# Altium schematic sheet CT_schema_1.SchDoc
size 886 x 812 mm
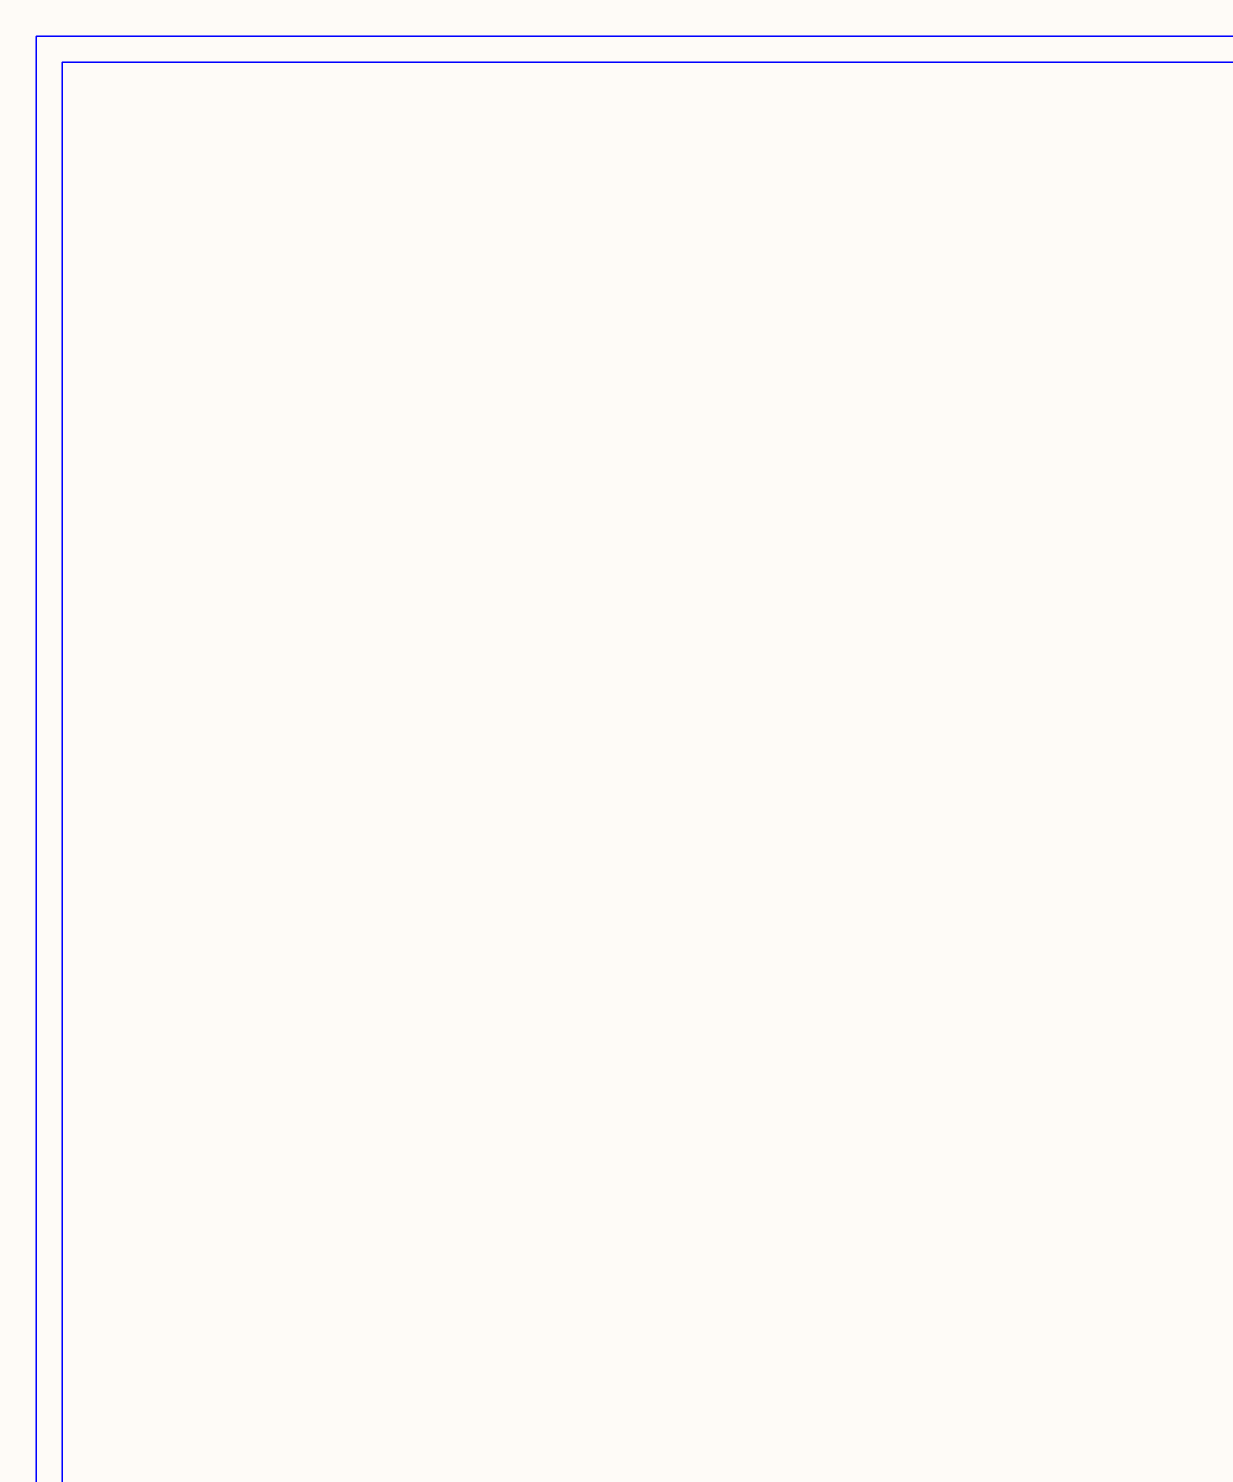
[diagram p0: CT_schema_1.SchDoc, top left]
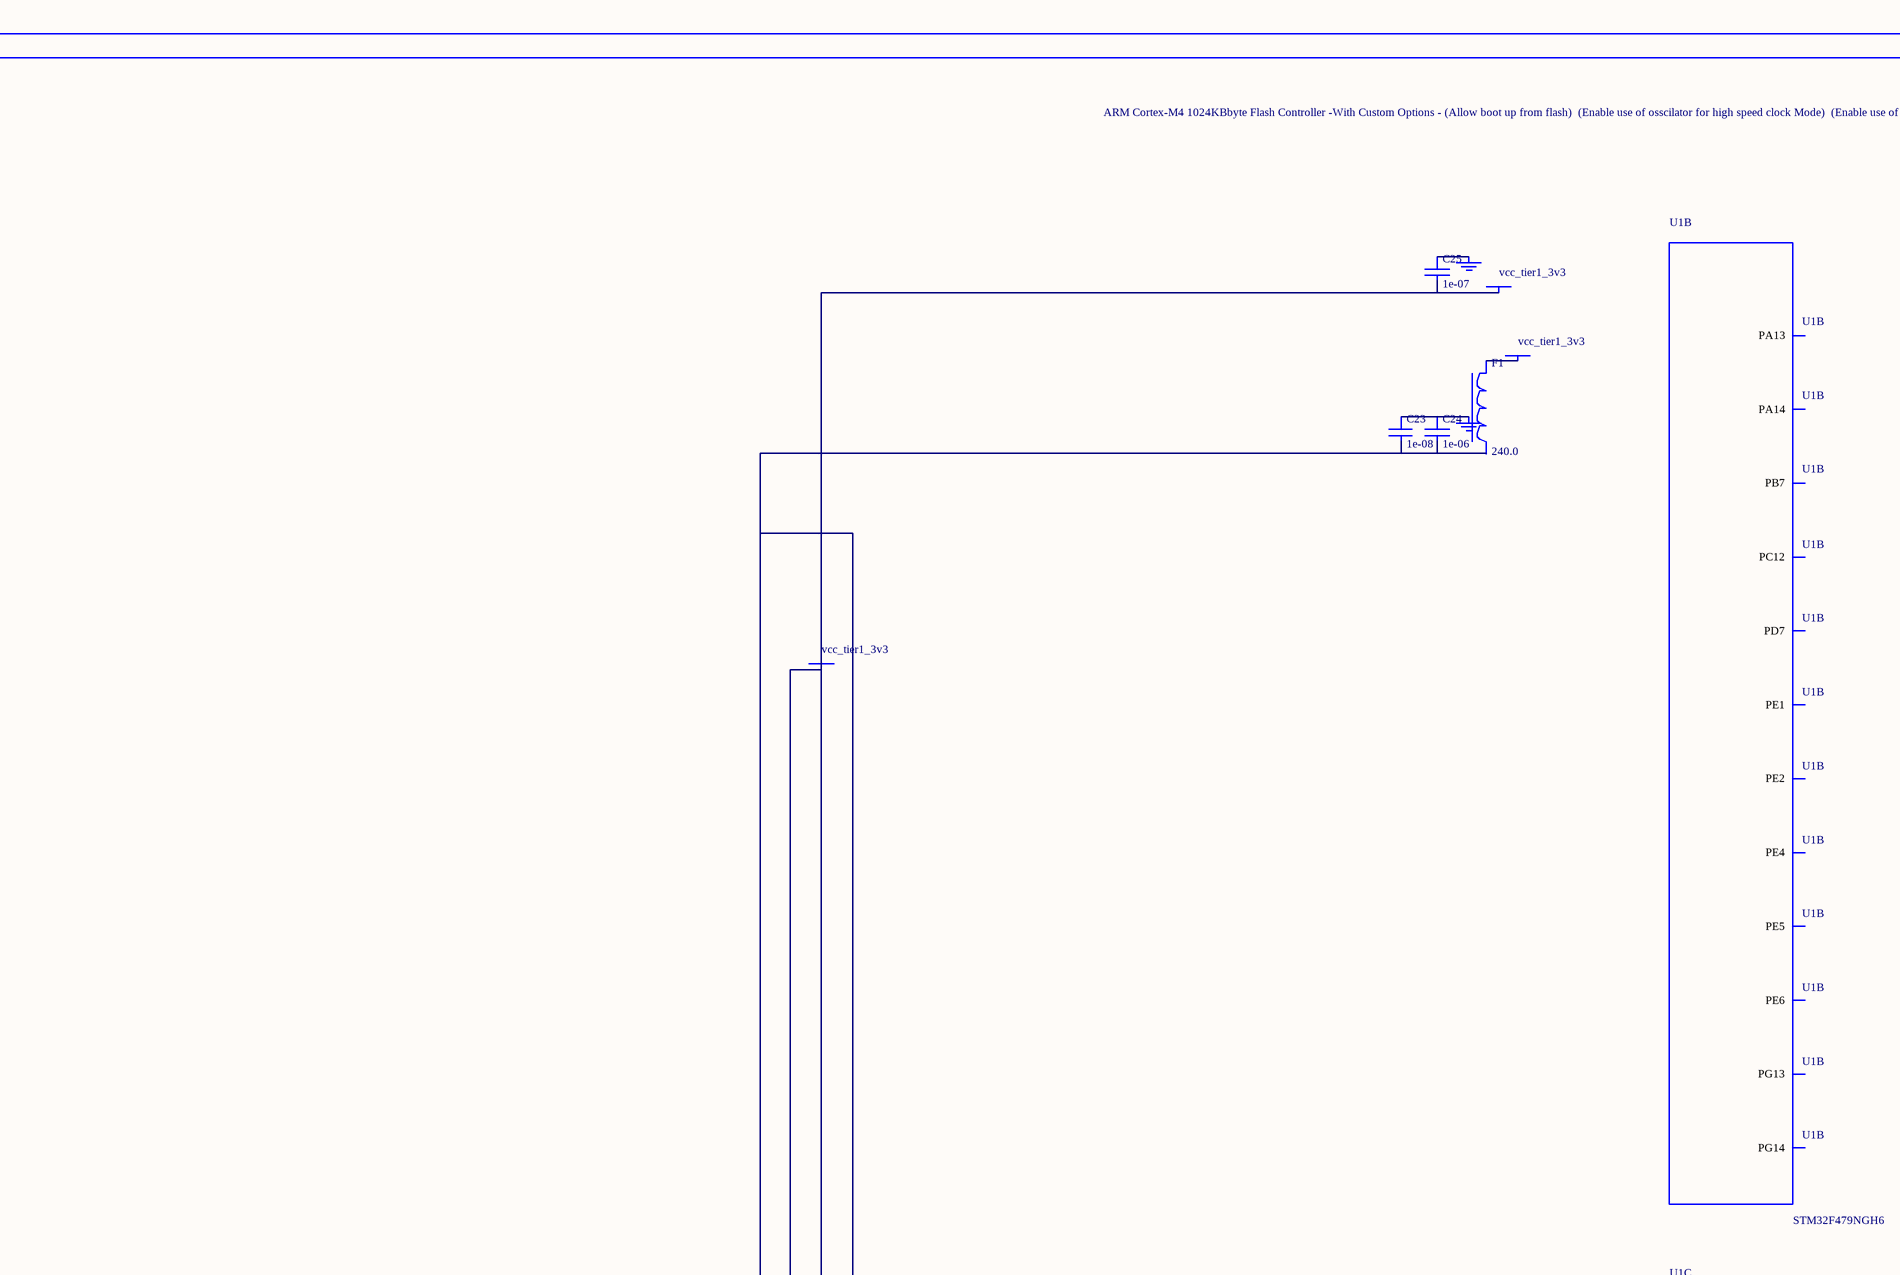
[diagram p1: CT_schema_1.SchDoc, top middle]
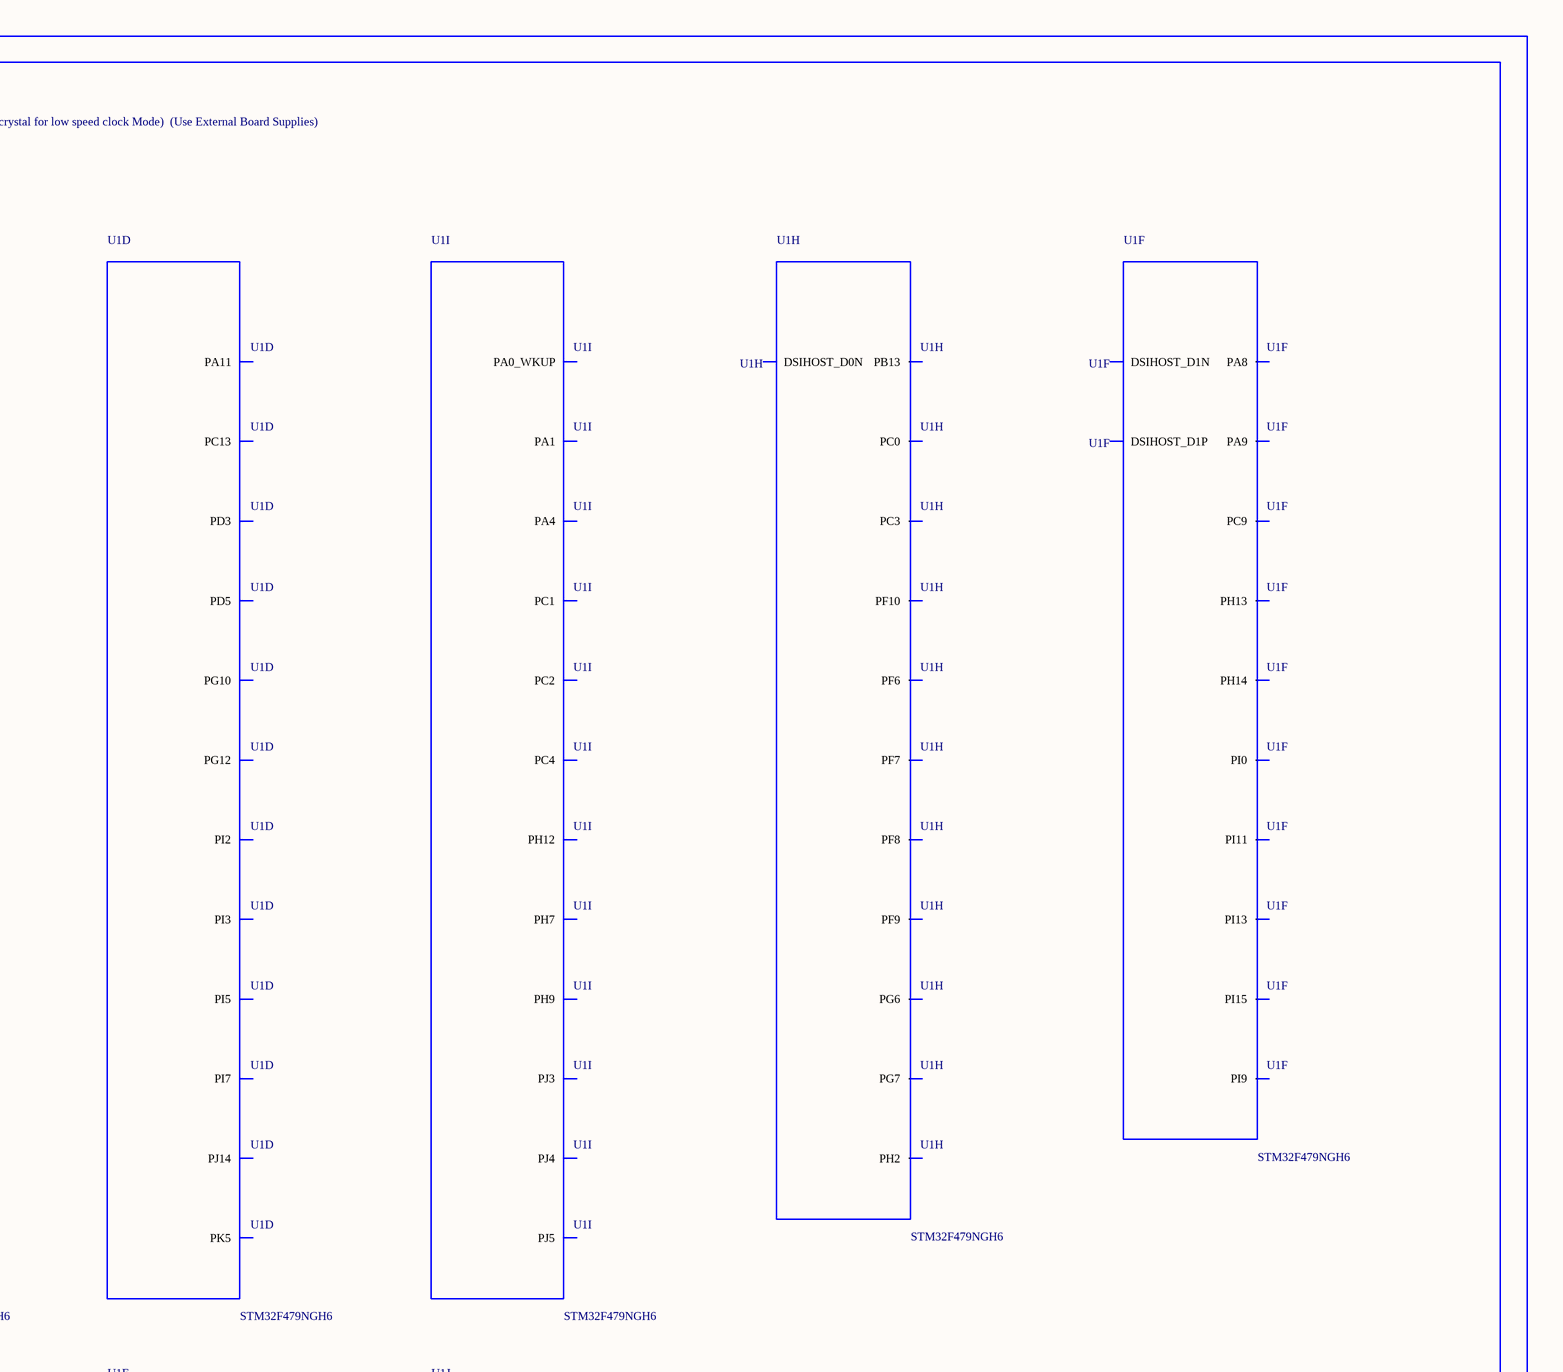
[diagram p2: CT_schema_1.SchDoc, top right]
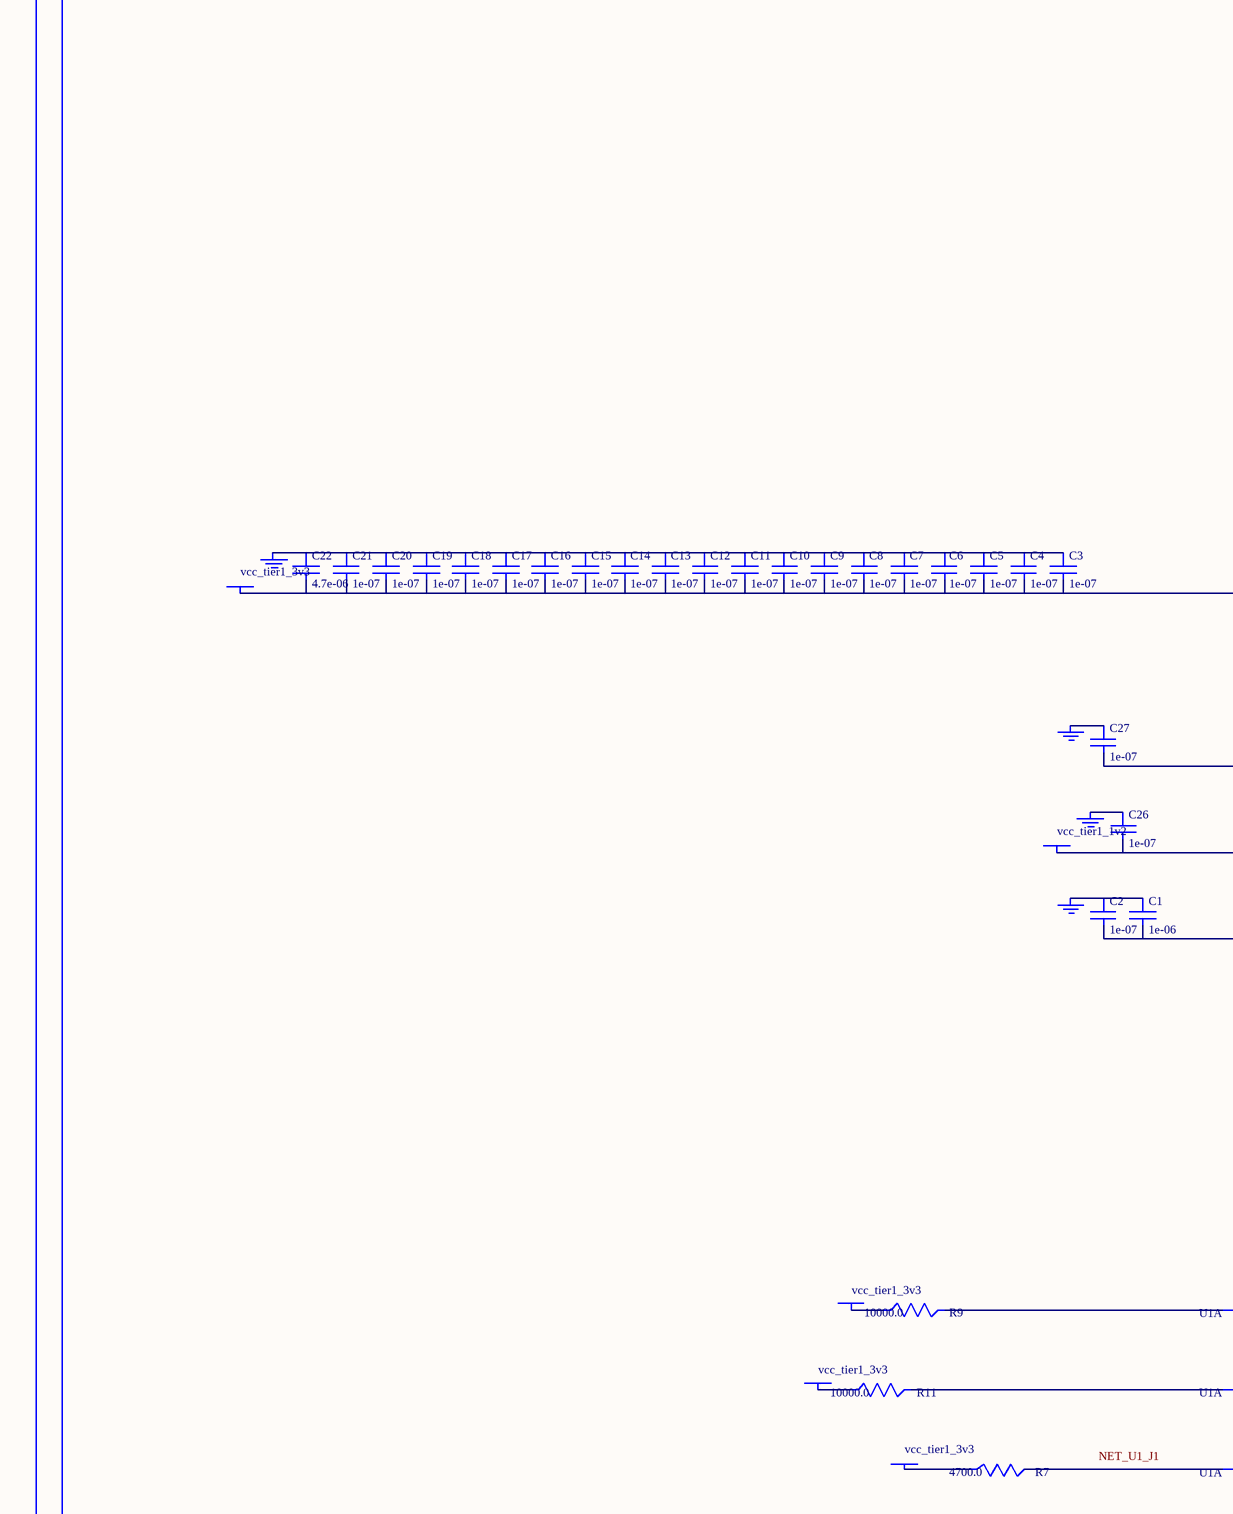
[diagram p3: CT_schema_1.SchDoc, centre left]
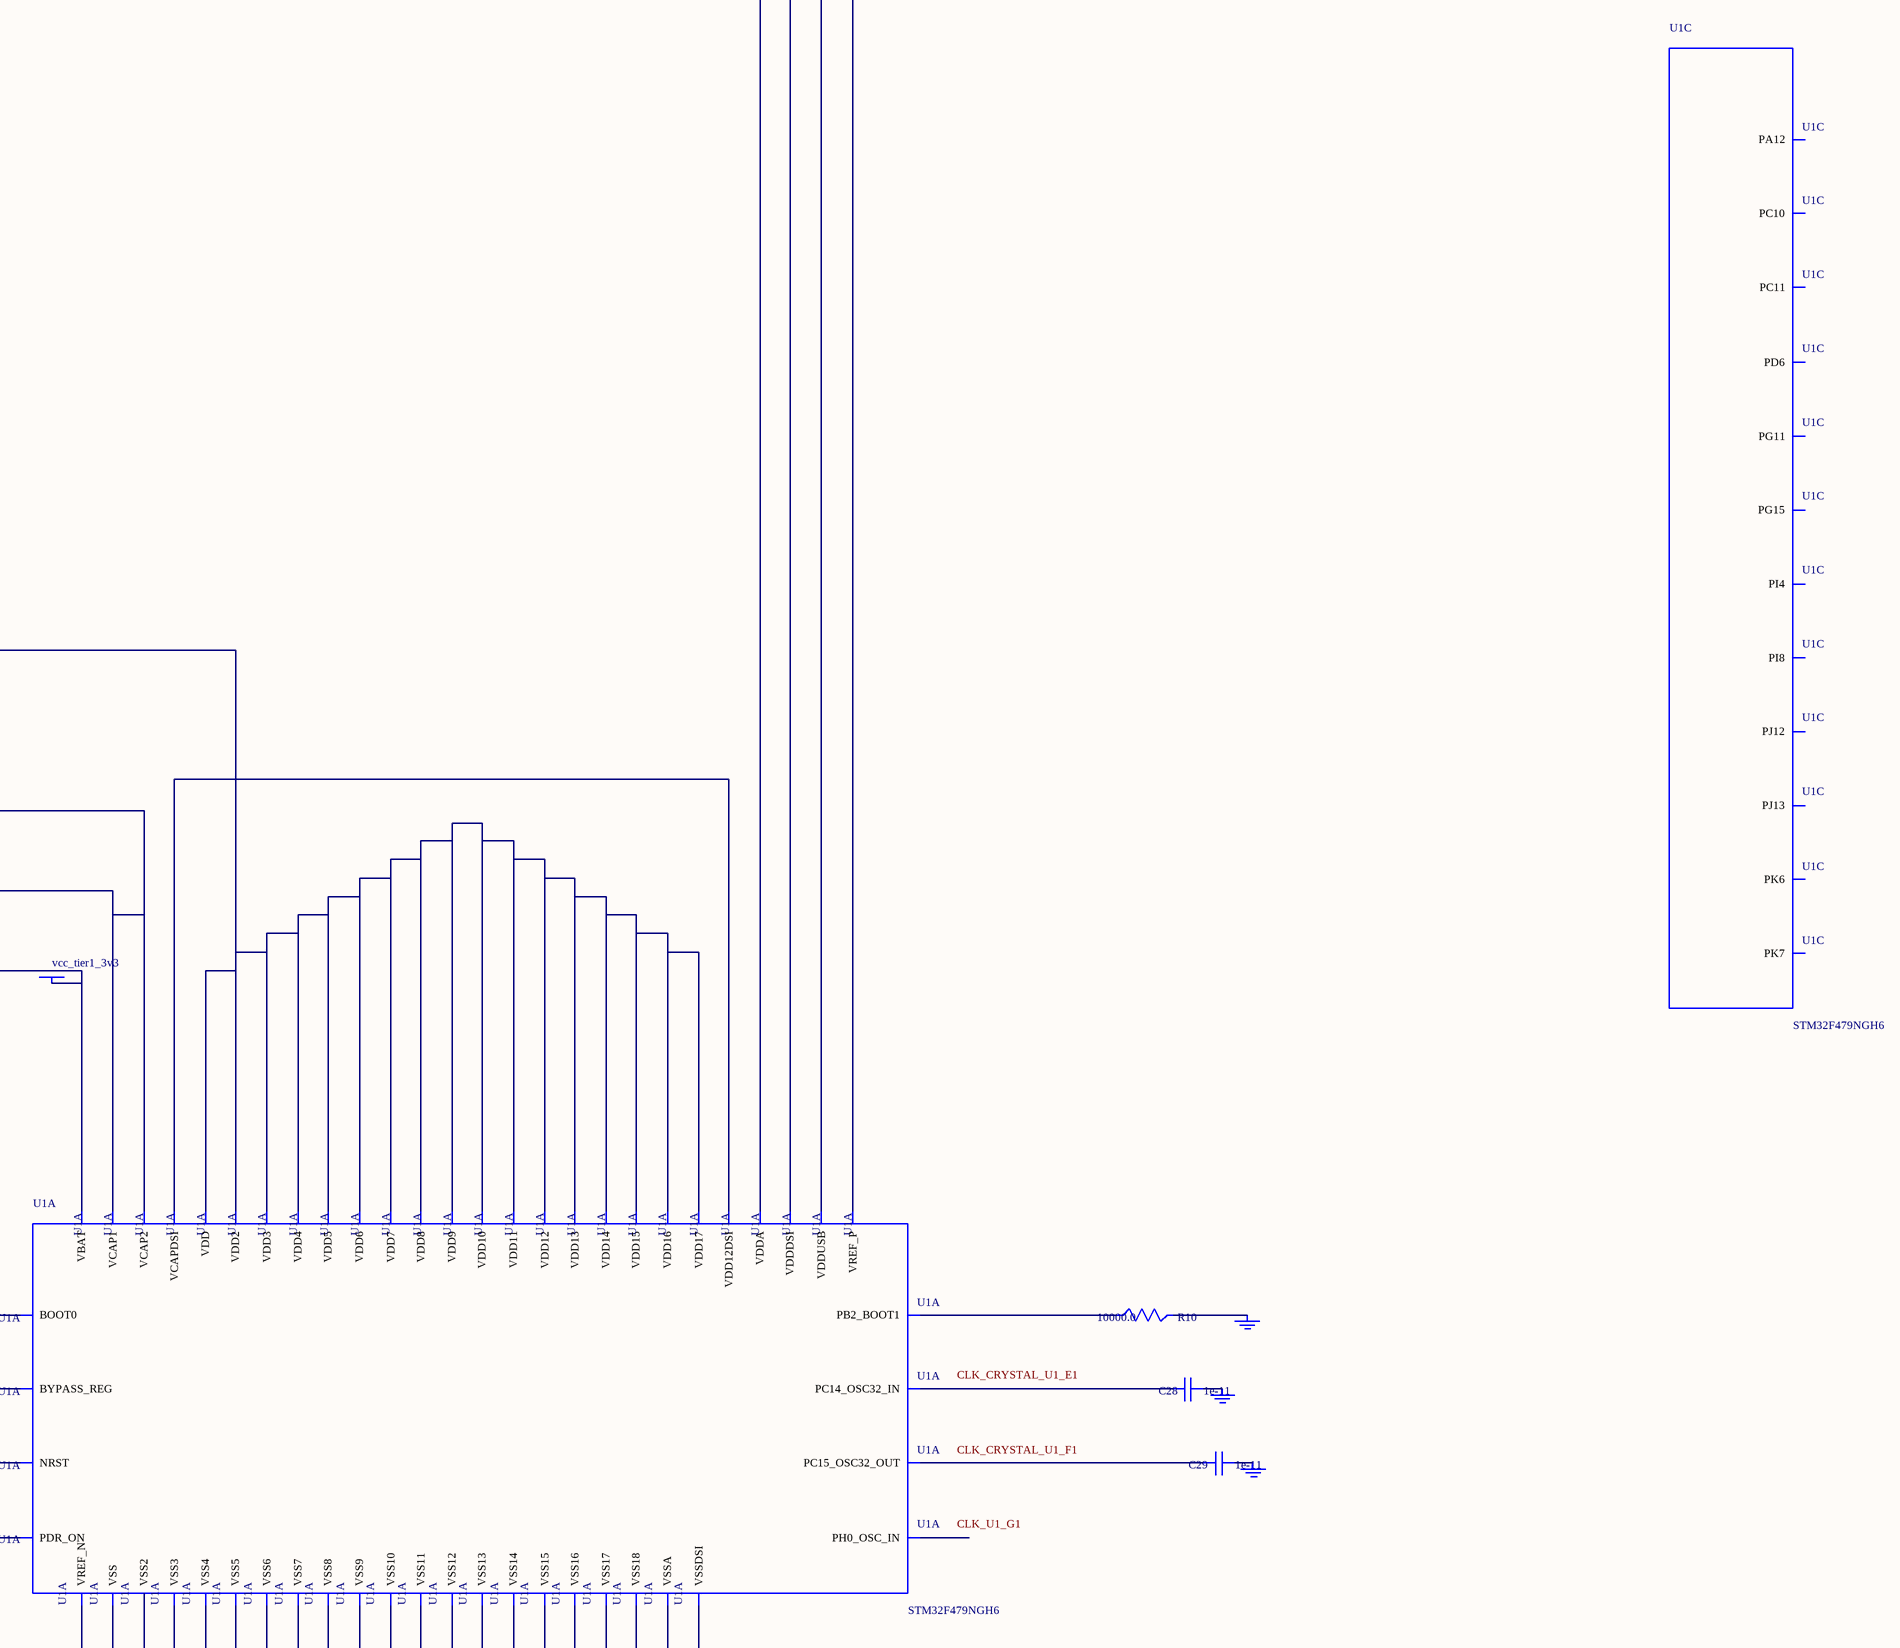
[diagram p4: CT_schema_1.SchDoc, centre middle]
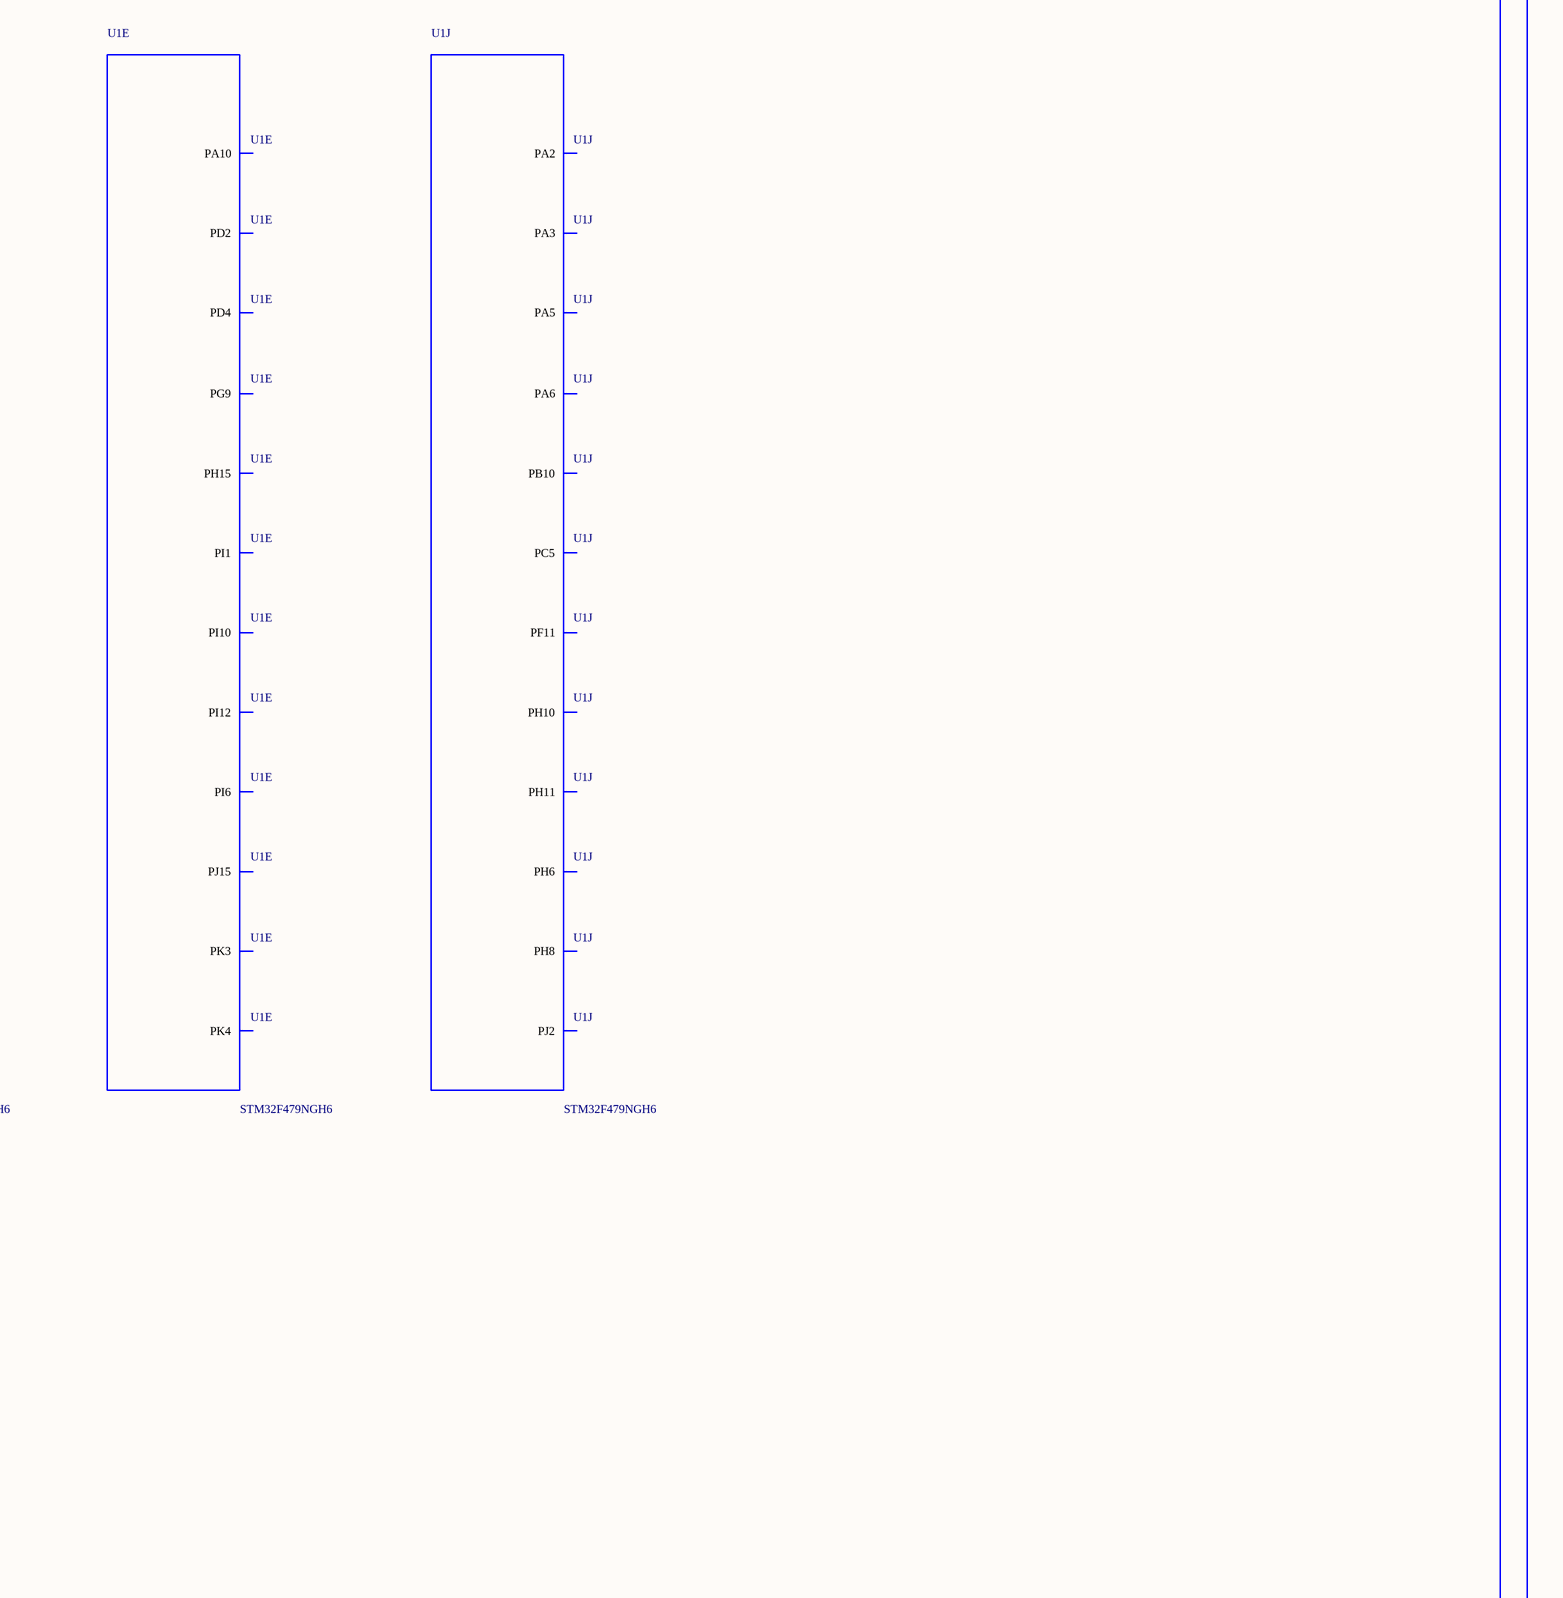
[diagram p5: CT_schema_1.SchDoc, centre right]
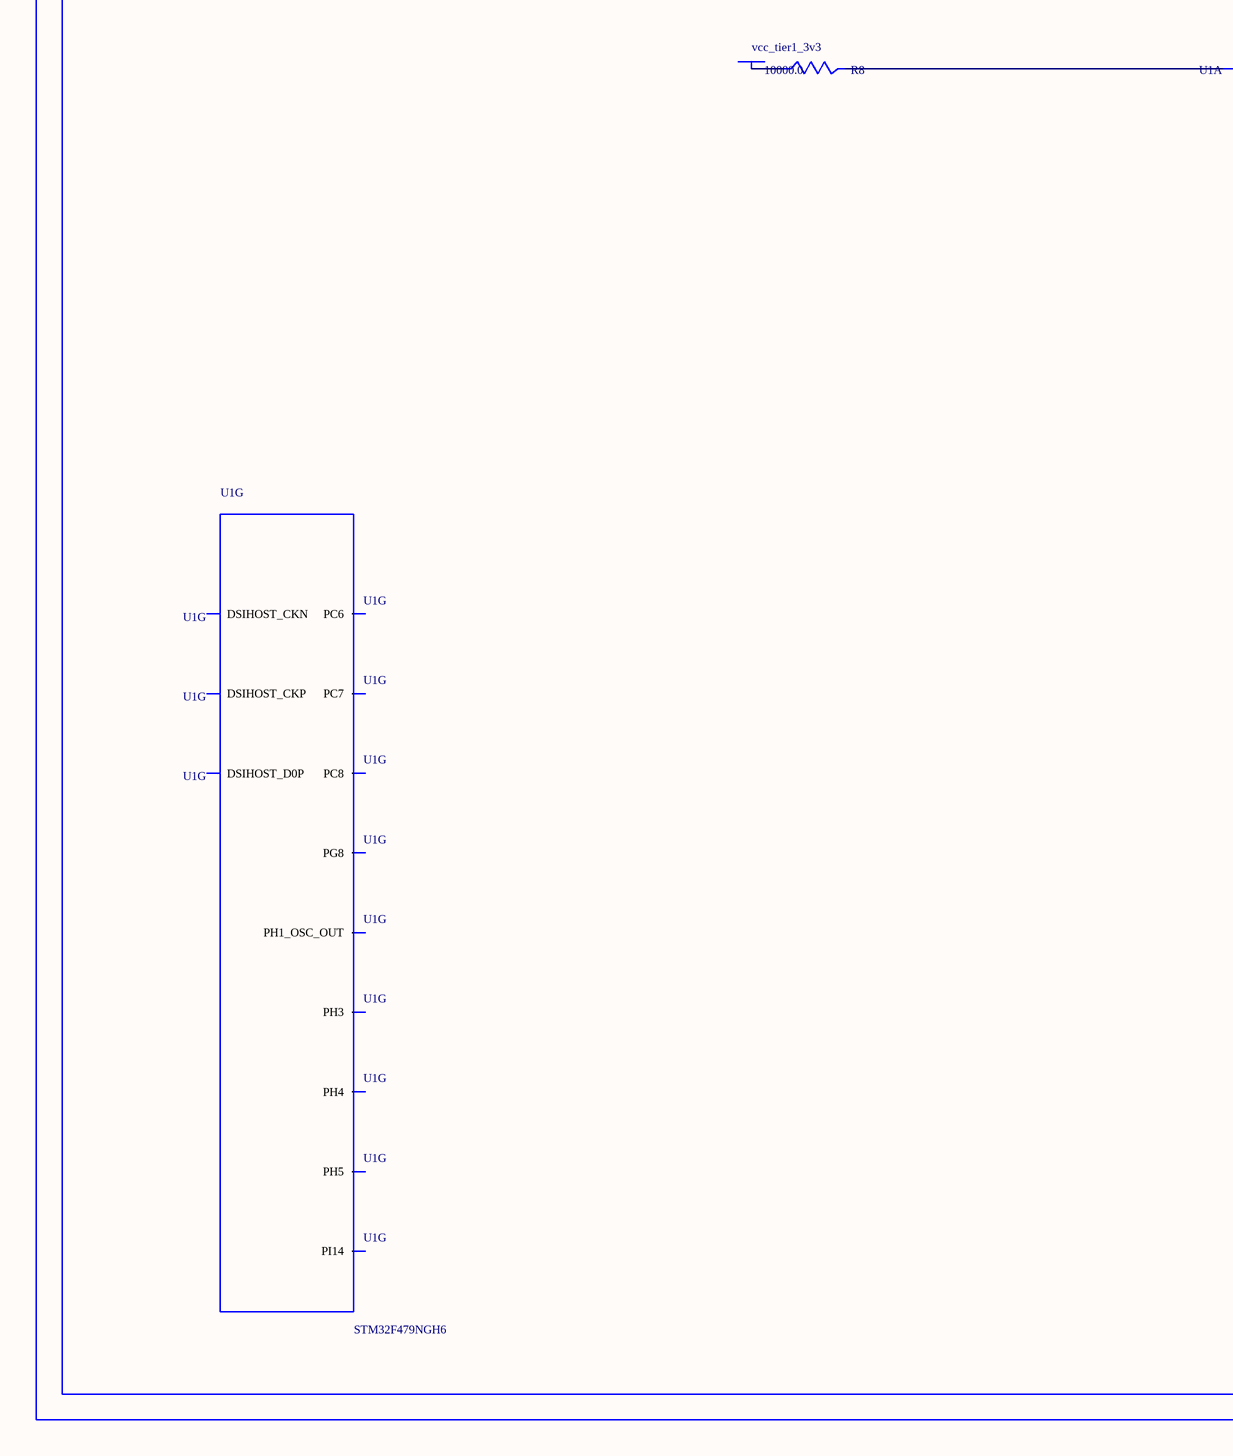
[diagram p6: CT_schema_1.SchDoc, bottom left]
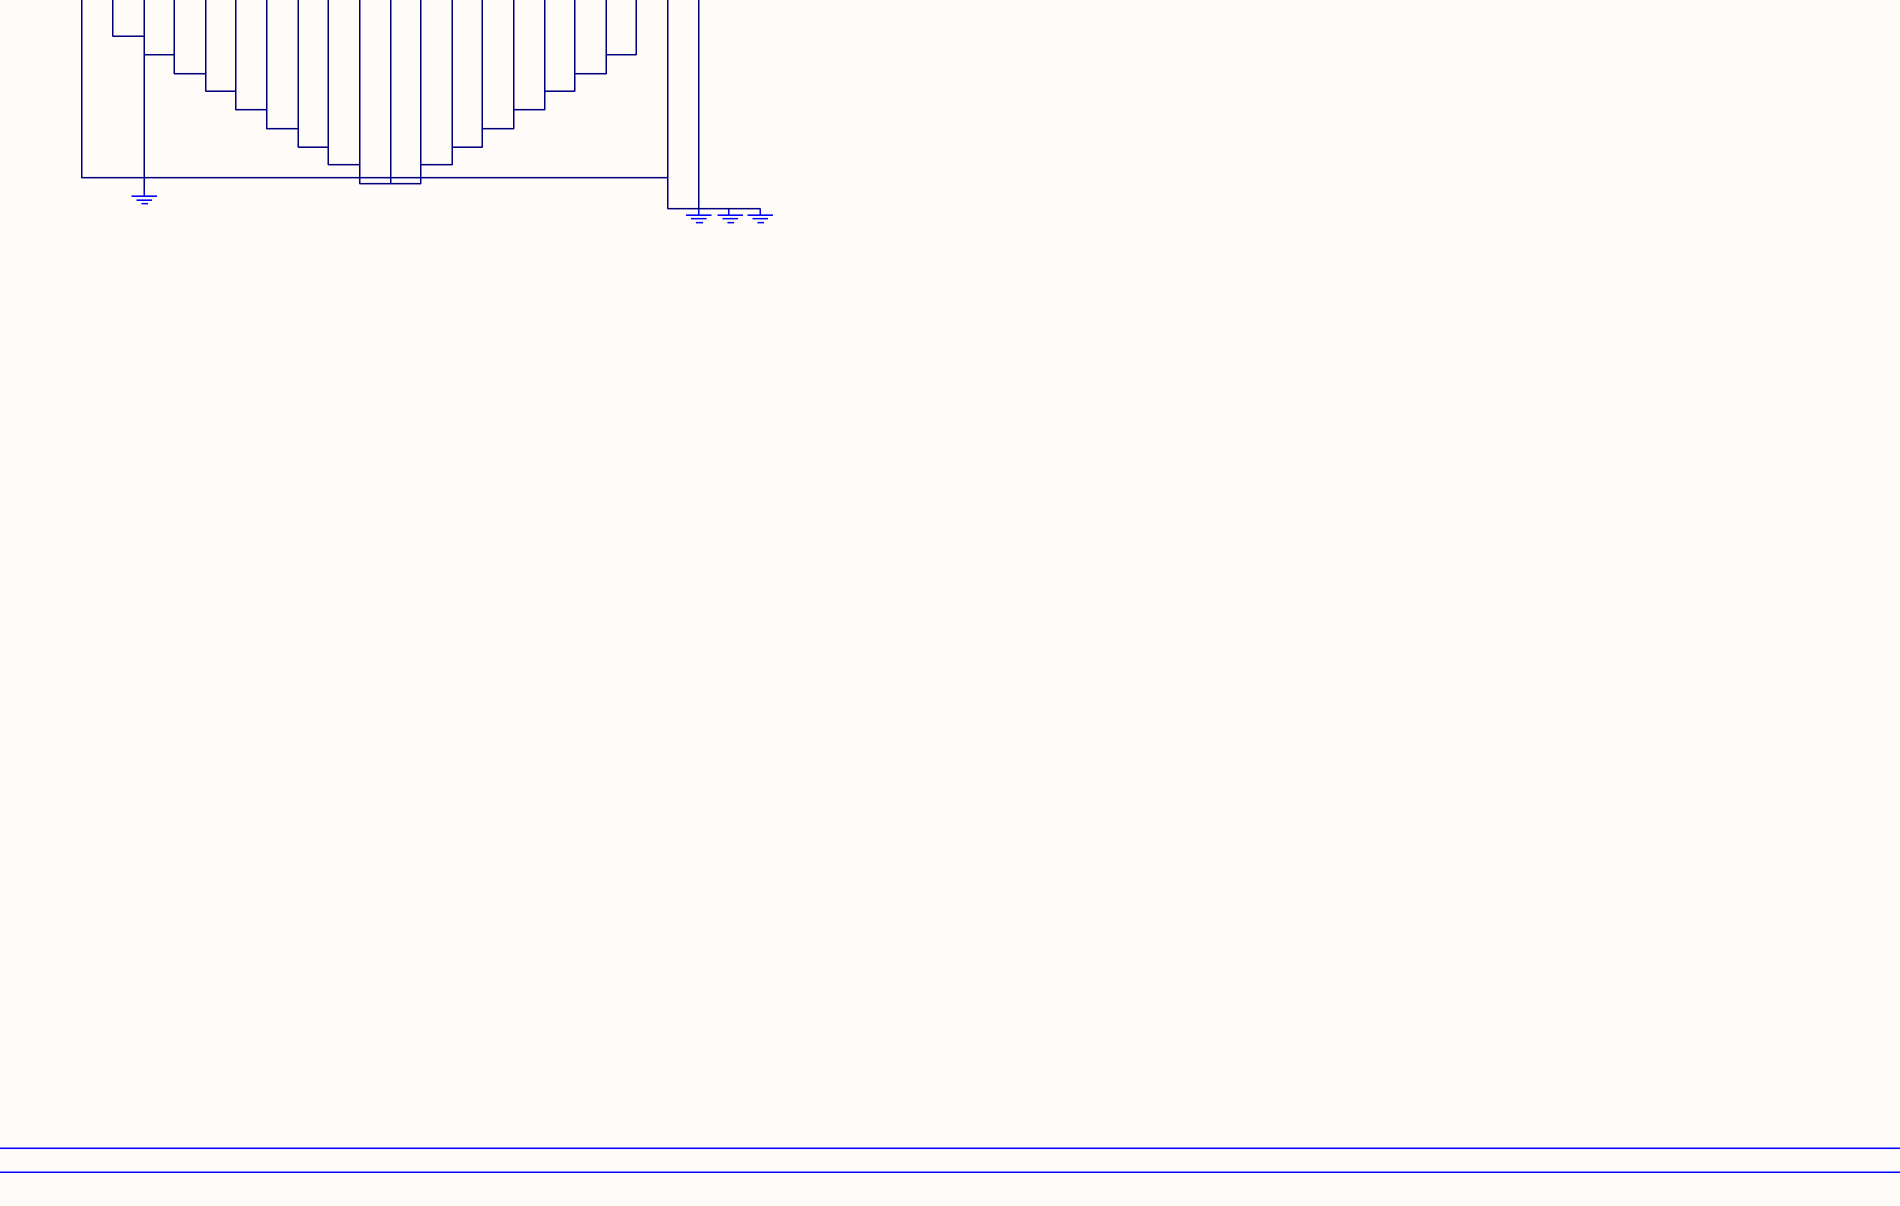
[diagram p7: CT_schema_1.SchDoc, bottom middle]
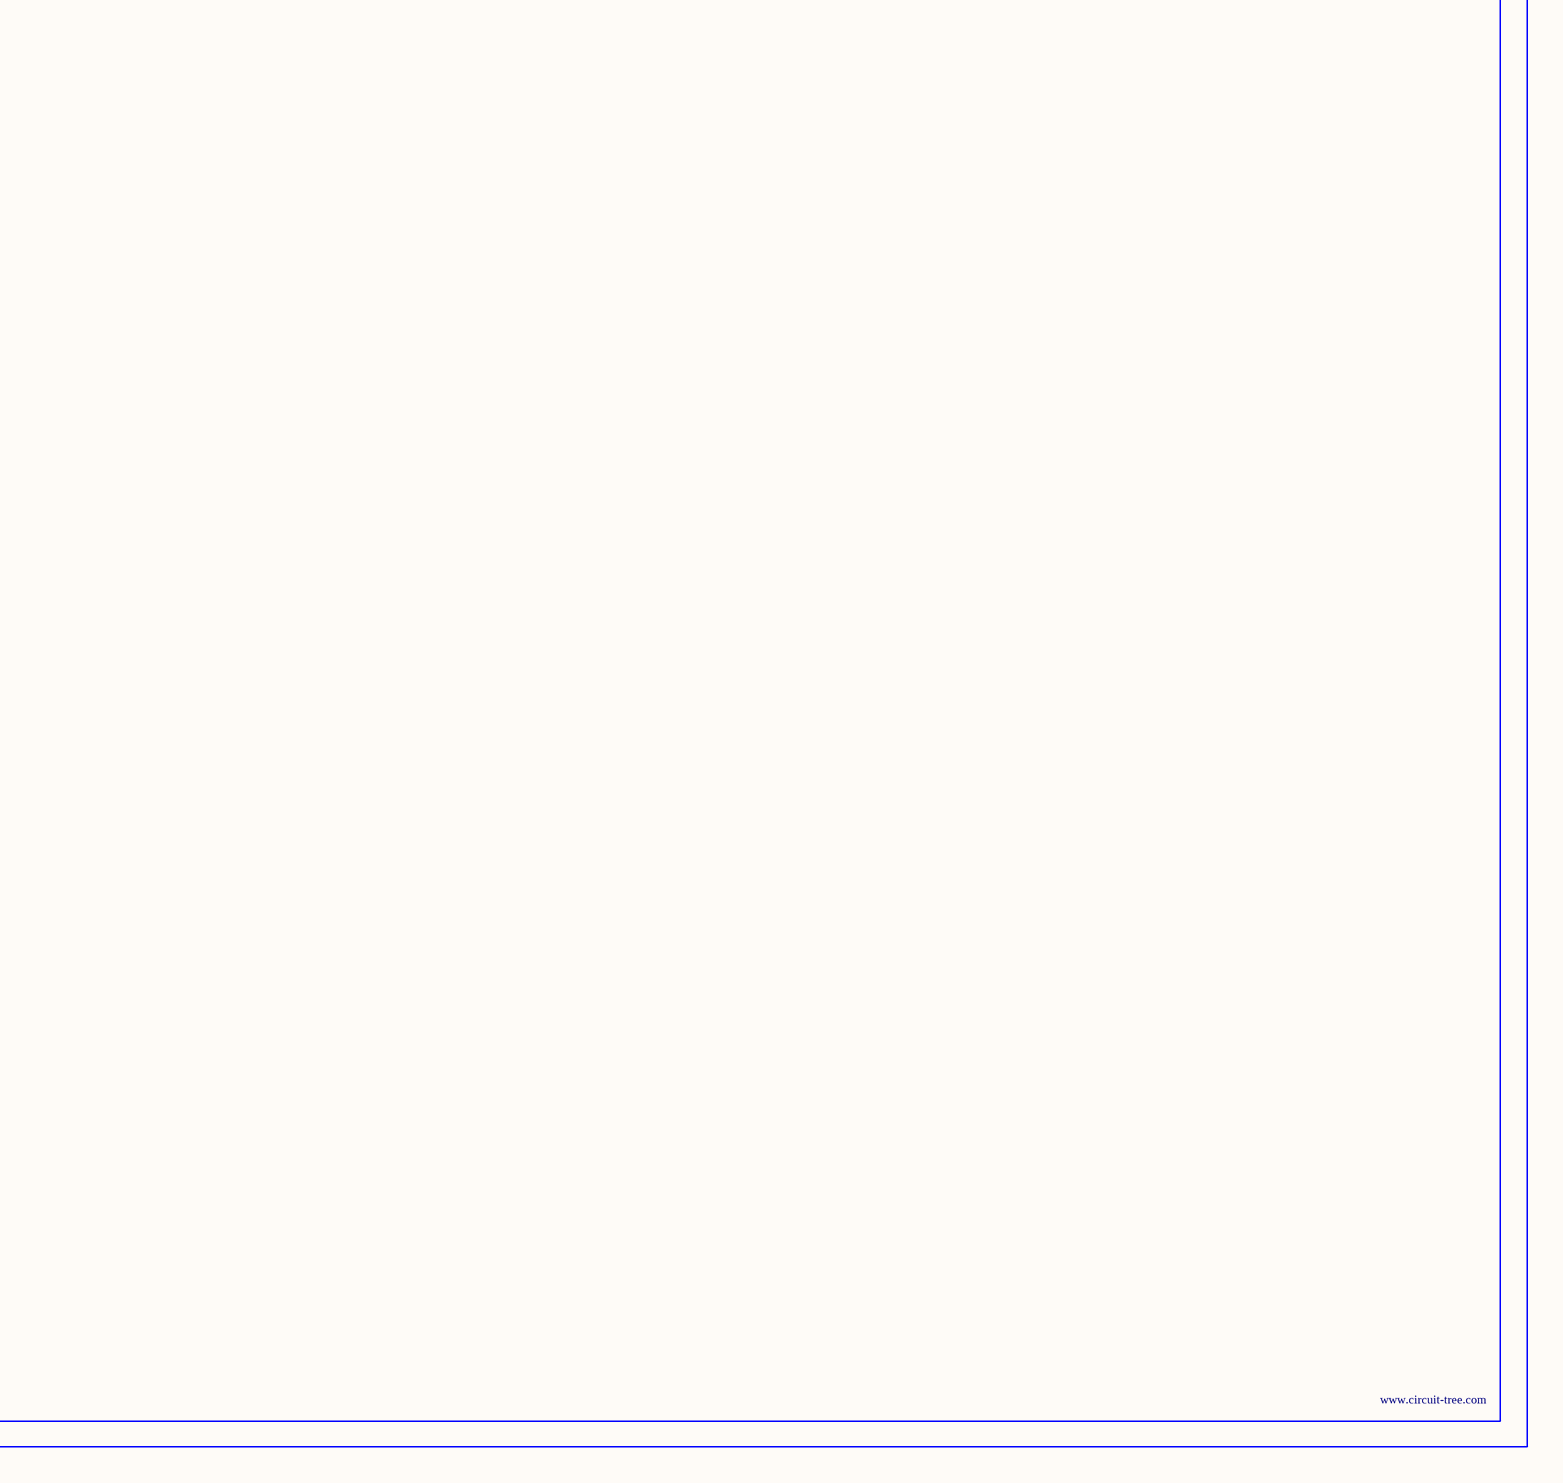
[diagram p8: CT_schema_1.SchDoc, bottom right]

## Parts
BORDER0  (no value)
C1  1e-06  [C0603]
C2  1e-07  [C0603]
C3  1e-07  [C0603]
C4  1e-07  [C0603]
C5  1e-07  [C0603]
C6  1e-07  [C0603]
C7  1e-07  [C0603]
C8  1e-07  [C0603]
C9  1e-07  [C0603]
C10  1e-07  [C0603]
C11  1e-07  [C0603]
C12  1e-07  [C0603]
C13  1e-07  [C0603]
C14  1e-07  [C0603]
C15  1e-07  [C0603]
C16  1e-07  [C0603]
C17  1e-07  [C0603]
C18  1e-07  [C0603]
C19  1e-07  [C0603]
C20  1e-07  [C0603]
C21  1e-07  [C0603]
C22  4.7e-06  [C0603]
C23  1e-08  [C0603]
C24  1e-06  [C0603]
C25  1e-07  [C0603]
C26  1e-07  [C0603]
C27  1e-07  [C0603]
C28  1e-11  [C0402]
C29  1e-11  [C0402]
F1  240.0  [L0603]
GND_INSTANCE_0_0  (no value)
GND_INSTANCE_0_1  (no value)
GND_INSTANCE_0_2  (no value)
GND_INSTANCE_0_3  (no value)
GND_INSTANCE_0_4  (no value)
GND_INSTANCE_0_5  (no value)
GND_INSTANCE_0_6  (no value)
GND_INSTANCE_0_7  (no value)
GND_INSTANCE_0_8  (no value)
GND_INSTANCE_0_9  (no value)
GND_INSTANCE_0_10  (no value)
GND_INSTANCE_0_11  (no value)
GND_INSTANCE_0_12  (no value)
POWER_INSTANCE_0_0  vcc_tier1_3v3
POWER_INSTANCE_0_1  vcc_tier1_3v3
POWER_INSTANCE_0_2  vcc_tier1_3v3
POWER_INSTANCE_0_3  vcc_tier1_3v3
POWER_INSTANCE_0_4  vcc_tier1_3v3
POWER_INSTANCE_0_5  vcc_tier1_3v3
POWER_INSTANCE_0_6  vcc_tier1_3v3
POWER_INSTANCE_0_7  vcc_tier1_1v2
POWER_INSTANCE_0_8  vcc_tier1_3v3
POWER_INSTANCE_0_9  vcc_tier1_3v3
R7  4700.0  [R0603]
R8  10000.0  [R0603]
R9  10000.0  [R0603]
R10  10000.0  [R0603]
R11  10000.0  [R0603]
U1  STM32F479NGH6  [TFBGA216]  (parts A,B,C,D,E,F,G,H,I,J of 15)

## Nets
NetC1_1: C1.1 C2.1 GND_INSTANCE_0_0.0(GND)
NetC1_2: C1.2 C2.2 POWER_INSTANCE_0_0.0(PWR) U1.C1(VBAT)
NetC3_1: C3.1 C4.1 C5.1 C6.1 C7.1 C8.1 C9.1 C10.1 C11.1 C12.1 C13.1 C14.1 C15.1 C16.1 C17.1 C18.1 C19.1 C20.1 C21.1 C22.1 GND_INSTANCE_0_2.0(GND)
NetC3_2: C3.2 C4.2 C5.2 C6.2 C7.2 C8.2 C9.2 C10.2 C11.2 C12.2 C13.2 C14.2 C15.2 C16.2 C17.2 C18.2 C19.2 C20.2 C21.2 C22.2 POWER_INSTANCE_0_2.0(PWR) U1.E7(VDD2) U1.E8(VDD3) U1.E9(VDD4) U1.E10(VDD) U1.F4(VDD6) U1.F5(VDD7) U1.F11(VDD5) U1.G5(VDD8) U1.H5(VDD9) U1.J5(VDD11) U1.J11(VDD10) U1.K5(VDD13) U1.K11(VDD12) U1.L7(VDD15) U1.L8(VDD16) U1.L9(VDD17) U1.L10(VDD14)
NetC23_1: C23.1 C24.1 GND_INSTANCE_0_1.0(GND)
NetC23_2: C23.2 C24.2 U1.P1(VREF_P) U1.R1(VDDA)
NetC25_1: C25.1 GND_INSTANCE_0_3.0(GND)
NetC25_2: C25.2 POWER_INSTANCE_0_4.0(PWR) POWER_INSTANCE_0_8.0(PWR) U1.G11(VDDUSB) U1.H11(VDDDSI)
NetC26_1: C26.1 GND_INSTANCE_0_5.0(GND)
NetC26_2: C26.2 C27.2 POWER_INSTANCE_0_7.0(PWR) U1.E11(VCAP2) U1.L11(VCAP1)
NetC27_1: C27.1 GND_INSTANCE_0_6.0(GND)
NetC28_1: C28.1 GND_INSTANCE_0_7.0(GND)
NetC28_2: C28.2 U1.E1(PC14_OSC32_IN)
NetC29_1: C29.1 GND_INSTANCE_0_8.0(GND)
NetC29_2: C29.2 U1.F1(PC15_OSC32_OUT)
NetF1_1: F1.1 POWER_INSTANCE_0_1.0(PWR)
NetGND_INSTANCE_0_4_0: GND_INSTANCE_0_4.0(GND) R10.2
NetGND_INSTANCE_0_9_0: GND_INSTANCE_0_9.0(GND) GND_INSTANCE_0_10.0(GND) GND_INSTANCE_0_11.0(GND) U1.G12(VSSDSI) U1.M1(VSSA) U1.N1(VREF_N)
NetGND_INSTANCE_0_12_0: GND_INSTANCE_0_12.0(GND) U1.F2(VSS2) U1.F6(VSS3) U1.F7(VSS4) U1.F8(VSS5) U1.F9(VSS6) U1.F10(VSS) U1.G6(VSS8) U1.G10(VSS7) U1.H6(VSS10) U1.H10(VSS9) U1.J6(VSS12) U1.J10(VSS11) U1.K6(VSS14) U1.K7(VSS15) U1.K8(VSS16) U1.K9(VSS17) U1.K10(VSS13) U1.L6(VSS18)
NetPOWER_INSTANCE_0_3_0: POWER_INSTANCE_0_3.0(PWR) R8.1
NetPOWER_INSTANCE_0_5_0: POWER_INSTANCE_0_5.0(PWR) R9.1
NetPOWER_INSTANCE_0_6_0: POWER_INSTANCE_0_6.0(PWR) R11.1
NetPOWER_INSTANCE_0_9_0: POWER_INSTANCE_0_9.0(PWR) R7.1
NetR7_2: R7.2 U1.J1(NRST)
NetR8_2: R8.2 U1.E5(PDR_ON)
NetR9_2: R9.2 U1.E6(BOOT0)
NetR10_1: R10.1 U1.M5(PB2_BOOT1)
NetR11_2: R11.2 U1.L5(BYPASS_REG)
NetU1_G13: U1.G13(VDD12DSI) U1.K12(VCAPDSI)

Not connected (* = marked no-connect by the designer): F1 2; U1 A1(PE4) A3(PE2) A4(PG14) A5(PE1) A11(PD7) A12(PC12) A14(PA14) A15(PA13) B1(PE5) B2(PE6) B3(PG13) B5(PB7) B7(PG15) B8(PG11) B9(PJ13) B10(PJ12) B11(PD6) B13(PC11) B14(PC10) B15(PA12) C2(PI8) C3(PI4) C4(PK7) C5(PK6) C6(PK5) C7(PG12) C8(PG10) C9(PJ14) C10(PD5) C11(PD3) C13(PI3) C14(PI2) C15(PA11) D1(PC13) D3(PI5) D4(PI7) D5(PI10) D6(PI6) D7(PK4) D8(PK3) D9(PG9) D10(PJ15) D11(PD4) D12(PD2) D13(PH15) D14(PI1) D15(PA10) E3(PI12) E4(PI9) E12(PH13) E13(PH14) E14(PI0) E15(PA9) F3(PI11) F12(DSIHOST_D1P) F13(DSIHOST_D1N) F14(PC9) F15(PA8) G1(PH0_OSC_IN) G3(PI13) G4(PI15) G14(PC8) G15(PC7) H1(PH1_OSC_OUT) H3(PI14) H4(PH4) H12(DSIHOST_CKP) H13(DSIHOST_CKN) H14(PG8) H15(PC6) J3(PH5) J4(PH3) J12(DSIHOST_D0P) J13(DSIHOST_D0N) J14(PG7) J15(PG6) K1(PF7) K2(PF6) K4(PH2) K14(PB13) L1(PF10) L2(PF9) L3(PF8) L4(PC3) M2(PC0) M3(PC1) M4(PC2) M9(PJ4) M14(PJ5) M15(PH12) N2(PA1) N3(PA0_WKUP) N4(PA4) N5(PC4) N8(PJ3) N13(PH7) N14(PH9) N15(PH11) P2(PA2) P3(PA6) P4(PA5) P5(PC5) P7(PJ2) P8(PF11) P12(PB10) P13(PH6) P14(PH8) P15(PH10) R2(PA3)

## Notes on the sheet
- Labels drawn without touching a wire or pin: CLK_CRYSTAL_U1_E1, CLK_CRYSTAL_U1_F1, CLK_U1_G1, NET_U1_J1

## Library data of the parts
BORDER0 = BORDER_PAGE0
C1 C24 = C0603C105K3RACTU
C2-C21 C25-C27 = 06035C104K4Z2A
C22 = GRM188R6YA475KE15D
C23 = 06035C103K4Z2A
C28 C29 = C0402C100K3GACTU
F1 = Z0603C241ASMST
GND_INSTANCE_0_0-GND_INSTANCE_0_12 = GND
POWER_INSTANCE_0_0-POWER_INSTANCE_0_9 = PWR
R7 = RC0603JR-074K7L
R8-R11 = RC0603JR-0710KL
